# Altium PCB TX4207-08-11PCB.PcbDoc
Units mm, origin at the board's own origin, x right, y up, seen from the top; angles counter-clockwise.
Board outline 46 x 26 mm, 2 copper layers (Top Layer, Bottom Layer); 14 components, 7 nets, 48 pads, 60 vias.
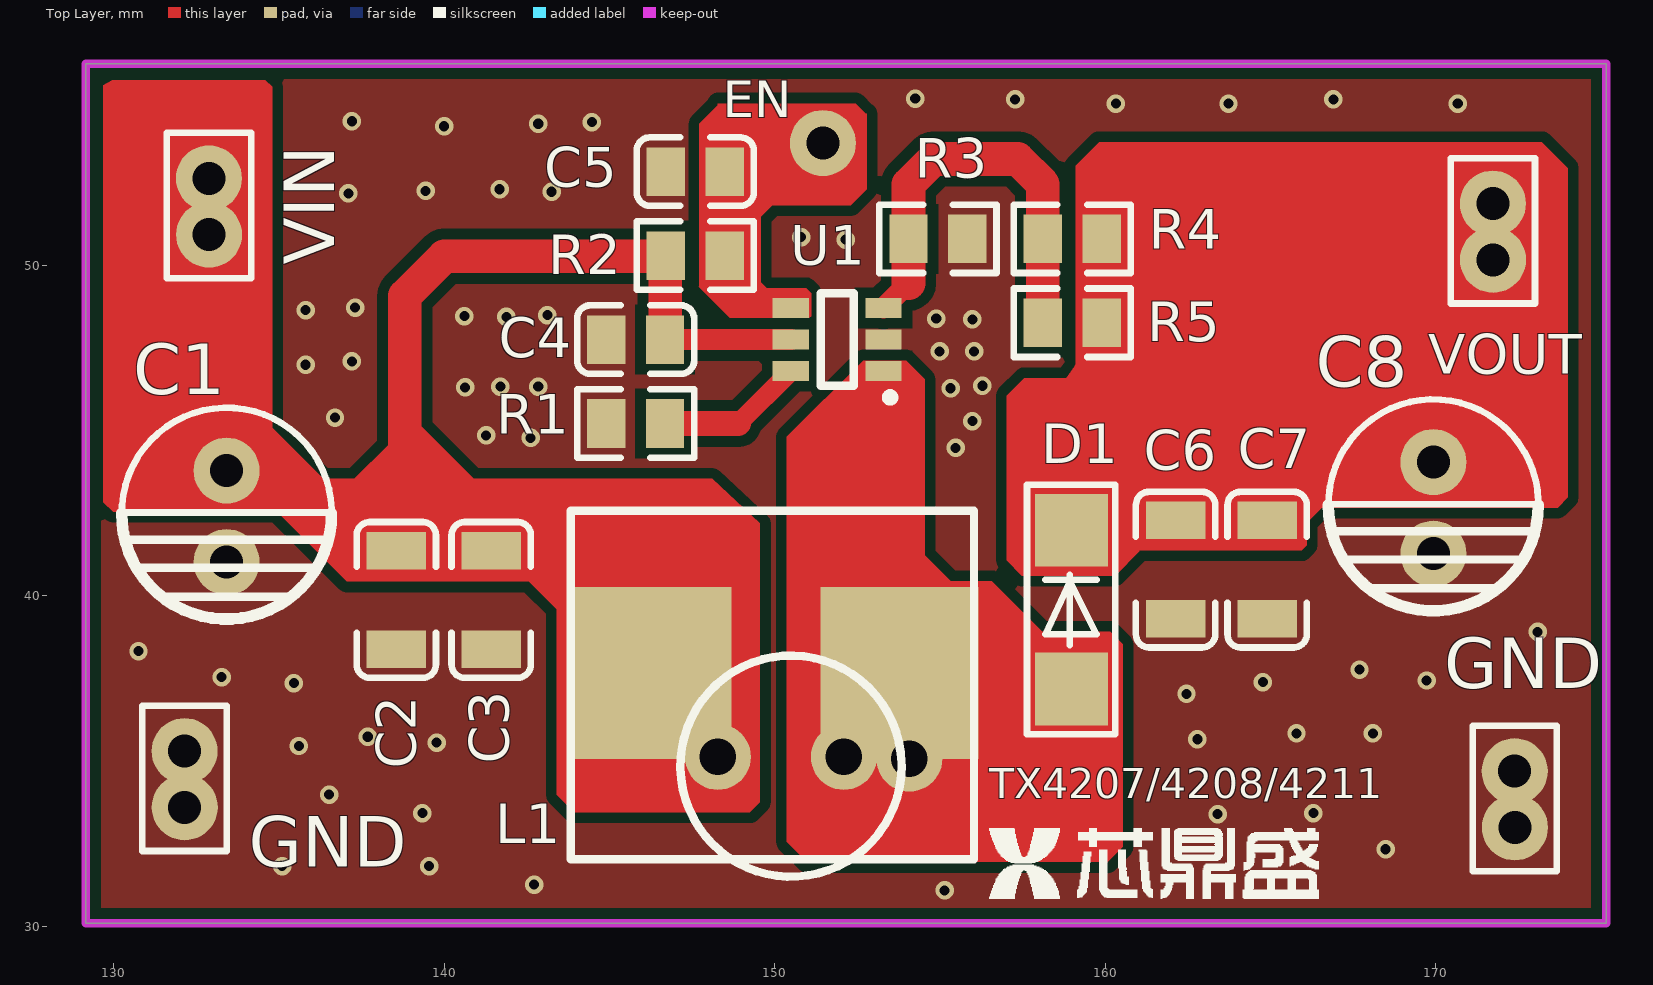
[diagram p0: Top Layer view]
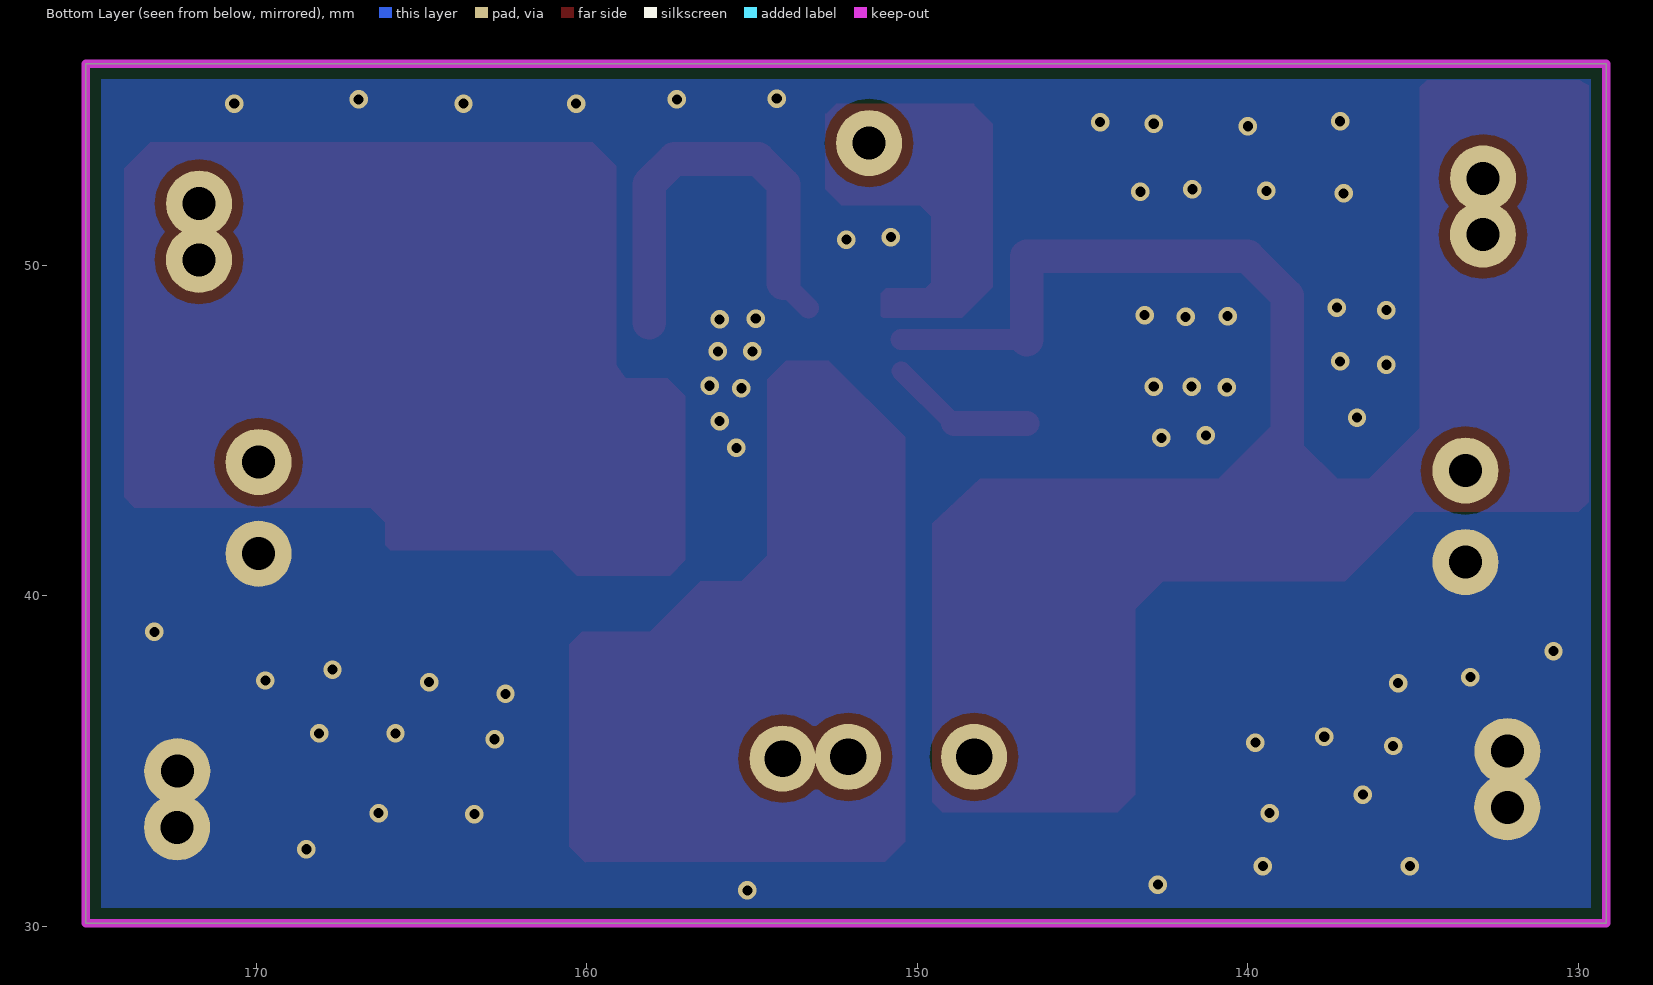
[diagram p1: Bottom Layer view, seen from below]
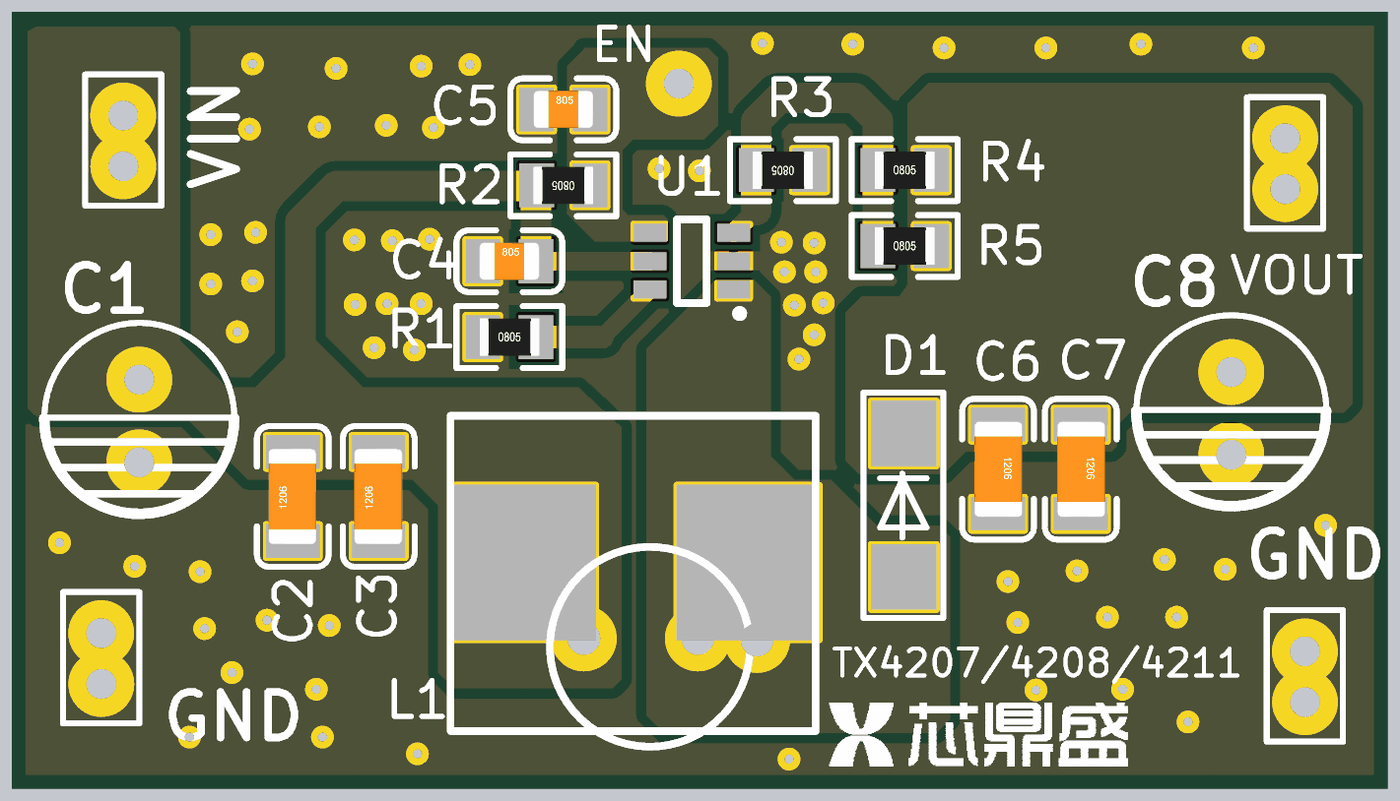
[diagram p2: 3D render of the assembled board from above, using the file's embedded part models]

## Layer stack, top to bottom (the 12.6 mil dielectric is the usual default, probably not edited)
Top Layer: signal copper 0.0356
Dielectric: dielectric 0.32, FR-4, Dk 4.8
Bottom Layer: signal copper 0.0356

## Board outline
129.159,30.099 175.159,30.099 175.159,56.099 129.159,56.099

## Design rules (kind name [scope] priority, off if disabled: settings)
Clearance [All] p1: gap=0.33
PolygonConnect [All] p1: connectstyle=Direct reliefconductorwidth=0.254 reliefentries=4 polygonreliefangle="90 Angle"
RoutingVias [All] p1: holewidth=0.711 width=1.27 viastyle="Through Hole" minholewidth=0.711 minwidth=1.27 maxholewidth=0.711 maxwidth=1.27
SilkscreenOverComponentPads [All] p1: minsilkscreentomaskgap=0.254
SolderMaskExpansion [All] p1: expansion=0.102
TestPointUsage [All] p1: valid=0 allowmultiple=FALSE
Testpoint [All] p1: side=15 testpointundercomponent=TRUE minsize=1.016 maxsize=2.54 preferedsize=1.524 minholesize=0 maxholesize=1.016 preferedholesize=0.813 testpointgrid=0.025 style=1023 order=0-112345678
Width [All] p1: maxlimit=2.54 minlimit=0.381 preferedwidth=0.381
23 further rules are at their usual default settings.

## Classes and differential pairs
component class TX4211: C1 C7 D1 L1 R4 R5 U1

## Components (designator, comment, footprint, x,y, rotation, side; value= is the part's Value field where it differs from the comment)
C2 "2.2uF (225) 10% 50V" 1206_C 138.557,39.878 r270 top (schematic designator C3)
C3 "2.2uF (225) 10% 50V" 1206_C 141.427,39.878 r270 top
C4 "Comment" 0805_C 145.796,47.752 r0 top
C5 "Comment" 0805_C 147.599,52.832 r0 top
C6 "2.2uF (225) 10% 50V" 1206_C 162.128,40.792 r90 top (schematic designator C3)
C7 "2.2uF (225) 10% 50V" 1206_C 164.897,40.792 r90 top (schematic designator C3)
D1 "" PCBComponent_1 158.928,43.18 r90 top
R1 "Comment" 0805_R 145.796,45.212 r0 top
R2 "Comment" 0805_R 147.599,50.292 r180 top
R3 "3.3KΩ (3301) ±1%" 0805_R 154.94,50.8 r180 top (schematic designator R2)
R4 "3.3KΩ (3301) ±1%" 0805_R 159.004,50.8 r0 top (schematic designator R1)
R5 "3.3KΩ (3301) ±1%" 0805_R 159.004,48.26 r0 top (schematic designator R1)
U1 "TX4207/08/11" SOT-23-6 151.892,47.752 r0 top
? "Comment" LOGO(10x2)mm 160.02,31.496 r0 top

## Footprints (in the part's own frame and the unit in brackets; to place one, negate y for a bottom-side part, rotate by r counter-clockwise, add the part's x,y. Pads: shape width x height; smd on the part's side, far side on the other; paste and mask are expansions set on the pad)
0805_C [mm]
  rect 1.16x1.47 smd: 1(-0.89,0) 2(0.89,0)
  silkscreen extent -1.77,-1.04 1.77,1.04, body extent -1,-0.62 1,0.63, height 0.77
0805_R [mm]
  rect 1.16x1.47 smd: 1(-0.89,0) 2(0.89,0)
  silkscreen extent -1.77,-1.04 1.77,1.03, body extent -1,-0.62 1,0.63, height 0.49
1206_C [mm]
  rect 1.13x1.8 smd: 1(-1.49,0) 2(1.49,0)
  silkscreen extent -2.36,-1.2 2.35,1.2, body extent -1.6,-0.81 1.6,0.79, height 1
LOGO(10x2)mm [mm]
  silkscreen extent -3.52,-0.65 6.44,1.47
PCBComponent_1 [mm]
  rect 2.2x2.2 smd: 1(-5.994,-0.051) 2(-1.194,-0.051)
  silkscreen extent -7.37,-1.37 0.18,1.3
SOT-23-6 [mm]
  rect 1.1x0.6 smd: 1(1.4,-0.95) 2(1.4,0) 3(1.4,0.95) 4(-1.4,0.95) 5(-1.4,0) 6(-1.4,-0.95)
  silkscreen extent -0.5,-1.87 1.73,1.4

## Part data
C2 C3 C6 C7: library part "1206 2.2uF (225) 10% 50V", "贴片电容"
D1: library part 二极管
R3 R4 R5: library part "0805 3.3KΩ (3301) 1%", "贴片电阻"
U1: library part Component_1

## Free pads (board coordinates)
  round 2 hole 1: 1(132.152,35.305) 1(132.156,33.604) 1(132.889,52.628) 1(132.893,50.927) 1(133.426,41.021) 1(133.426,43.79) 1(151.46,53.696) 1(169.926,41.275) 1(169.926,44.044) 1(171.725,51.866) 1(171.729,50.165) 1(172.386,34.696) 1(172.39,32.995)
  rect 4.78x5.2 smd: 1(146.304,37.668) 1(153.772,37.668)
  round 2 hole 1.1: 12(148.285,35.128) 12(152.095,35.128) 12(154.076,35.077)

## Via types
v1: diameter 0.559, hole 0.305, Top Layer to Bottom Layer, 60 vias

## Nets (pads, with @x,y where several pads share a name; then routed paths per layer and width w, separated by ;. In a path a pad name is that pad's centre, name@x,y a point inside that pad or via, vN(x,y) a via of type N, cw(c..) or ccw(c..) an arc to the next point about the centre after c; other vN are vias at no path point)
EN: C5.2 pad.1@151.46,53.696 R2.1 U1.4
FB: R3.2 R4.1 R5.1 U1.3 | length 12.9
  Top Layer w0.635: U1.3 154.05,49.46
  Top Layer w1.016: 154.05,49.46 R3.2 154.05,52.45 154.813,53.213 157.353,53.213 158.114,52.452 R4.1 R5.1
GND: C2.2 C3.2 C4.1 C5.1 C6.1 C7.1 pad.1@132.152,35.305 pad.1@132.156,33.604 pad.1@133.426,41.021 pad.1@169.926,41.275 pad.1@172.39,32.995 pad.1@172.386,34.696 R1.1 R3.1 U1.2
  other v1: 155.143,31.09 142.723,31.267 135.103,31.826 139.548,31.826 168.478,32.334 163.398,33.401 139.344,33.426 166.294,33.426 136.525,33.985 135.611,35.458 139.776,35.56 162.789,35.662 137.693,35.738 165.786,35.839 168.097,35.839 162.458,37.033 135.458,37.363 164.77,37.389 169.723,37.44 133.274,37.541 167.691,37.77 130.759,38.329 173.076,38.913 155.473,44.475 142.621,44.78 141.275,44.856 155.981,45.288 136.703,45.39 155.321,46.279 140.64,46.304 141.707,46.33 142.85,46.33 156.286,46.355 135.814,46.99 137.211,47.092 154.991,47.396 156.032,47.396 155.981,48.362 154.889,48.387 141.884,48.438 140.614,48.463 143.129,48.489 135.814,48.641 137.312,48.717 152.146,50.775 150.8,50.851 137.109,52.172 143.256,52.222 139.446,52.248 141.681,52.299 140.005,54.204 142.85,54.28 144.475,54.331 137.211,54.356 160.325,54.889 163.728,54.889 170.663,54.889 157.277,55.016 166.903,55.016 154.254,55.042
NC: R1.2 U1.6 | length 4.5
  Top Layer w0.584: 148.902,45.212 U1.6
  Top Layer w0.762: R1.2 148.902,45.212
NetC3_2: C6.2 C7.2 D1.2 pad.1@169.926,44.044 pad.1@171.725,51.866 pad.1@171.729,50.165 R4.2 R5.2
SW: D1.1 pad.1@153.772,37.668 pad.12@152.095,35.128 pad.12@154.076,35.077 U1.1
VDD: C2.1 C3.1 C4.2 pad.1@132.889,52.628 pad.1@132.893,50.927 pad.1@133.426,43.79 pad.1@146.304,37.668 pad.12@148.285,35.128 R2.2 U1.5 | length 20.4
  Top Layer w0.635: C4.2 U1.5
  Top Layer w1.016: 138.811,43.409 138.811,49.073 140.007,50.269 146.686,50.269 C4.2

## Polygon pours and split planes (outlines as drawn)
GND on Top Layer "Top Layer-No Net" (solid, remove dead copper, pour order 1000): 129.159,56.099 175.159,56.099 175.159,30.099 129.159,30.099 129.159,56.099
GND on Bottom Layer "Top Layer-No Net" (solid, remove dead copper, pour order 1001): 129.159,55.829 129.429,56.099 175.159,56.099 175.159,30.099 129.159,30.099 129.159,56.099

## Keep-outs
Keep-Out Layer:
  the board outline again, w0.254

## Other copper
Top Layer:
  region net VDD: 136.754,42.164 137.287,42.697 148.107,43.536 149.555,42.189 149.555,33.757 149.25,33.452 143.942,33.452 143.408,33.985 143.408,39.599 142.57,40.437 137.058,40.437 136.754,40.742
  region net VDD: 149.098,42.545 148.107,43.536 136.347,43.536 134.798,45.085 134.798,55.397 134.595,55.601 129.972,55.601 129.794,55.499 129.692,55.448 129.692,42.824 129.997,42.545
  region net VDD: 134.925,42.621 134.925,42.57 137.058,40.437 137.287,40.665 137.287,42.697 135.001,42.697
  region net VDD: 139.319,45.11 140.894,43.536 140.894,43.51 139.268,43.51 139.319,43.561
  region net VDD: 137.211,43.536 137.287,43.536 138.328,44.577 138.328,43.51 137.236,43.51
  region net EN: 147.726,54.28 148.285,54.839 148.285,54.889 152.451,54.889 152.756,54.585 152.781,54.585 152.781,52.299 152.298,51.816 148.133,51.816 147.726,52.222
  region net EN: 147.726,52.248 147.726,49.378 147.701,49.352 148.641,48.412 151.054,48.412 151.105,48.463 151.105,49.149 150.952,49.301 149.758,49.301 149.581,49.479 149.581,51.46 149.962,51.841 149.555,52.248
  region net NetC3_2: 159.106,53.01 159.817,53.721 173.203,53.721 173.99,52.934 173.99,42.977 173.685,42.672 166.548,42.672 166.091,42.215 166.091,41.529 165.938,41.377 161.036,41.377 161.036,41.351 160.299,40.615 157.48,40.615 157.023,41.072 157.023,46.05 157.556,46.584 158.826,46.584 159.08,46.939 159.106,47.015
  region net SW: 152.679,47.117 153.975,47.117 154.534,46.558 154.534,41.224 155.321,40.437 156.566,40.437 158.09,38.913 160.147,38.913 160.528,38.532 160.528,32.41 160.045,31.928 160.02,31.953 150.978,31.953 150.368,32.563 150.368,44.806

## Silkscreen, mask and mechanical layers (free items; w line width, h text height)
Top Overlay:
  lines w0.2: 130.353,42.52 136.576,42.52 ; 130.877,32.283 130.877,36.68 ; 130.886,32.283 133.401,32.283 ; 130.927,36.68 133.427,36.68 133.427,32.283 ; 131.614,49.606 131.614,54.003 ; 131.623,49.606 134.137,49.606 ; 131.664,54.003 134.164,54.003 134.164,49.606 ; 136.601,42.621 ccw(c133.428,42.515) 136.602,42.57 ; 166.853,42.774 173.076,42.774 ; 170.45,48.844 170.45,53.241 ; 170.459,48.844 172.974,48.844 ; 170.5,53.241 173,53.241 173,48.844 ; 171.111,31.674 171.111,36.071 ; 171.12,31.674 173.634,31.674 ; 171.161,36.071 173.661,36.071 173.661,31.674 ; 173.101,42.875 ccw(c169.928,42.769) 173.102,42.824
  lines w0.254: 130.5,41.696 136.5,41.696 ; 130.8,40.846 135.975,40.846 ; 131.575,39.971 135.325,39.971 ; 153.838,34.951 ccw(c150.495,34.849) 153.839,34.875 ; 167,41.95 173,41.95 ; 167.3,41.1 172.475,41.1 ; 168.075,40.225 171.825,40.225 ; 143.832,32.029 143.832,42.579 156.032,42.579 156.032,32.029 143.832,32.029
  lines w0.35: 130.251,42.494 ccw(c133.423,42.469) 136.595,42.494 ; 166.751,42.748 ccw(c169.923,42.723) 173.095,42.748
  text "EN" at 148.438,54.483 h1.1
  text "VIN" at 136.677,50.013 h1.52 r90
  text "VOUT" at 169.774,46.711 h1.2
  text "C8" at 166.37,46.33 h1.52
  text "C1" at 130.607,46.101 h1.52
  text "GND" at 170.256,37.211 h1.52
  text "TX4207/4208/4211" at 156.489,33.884 h0.9
  text "L1" at 141.554,32.512 h1.2
  text "GND" at 134.087,31.801 h1.52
